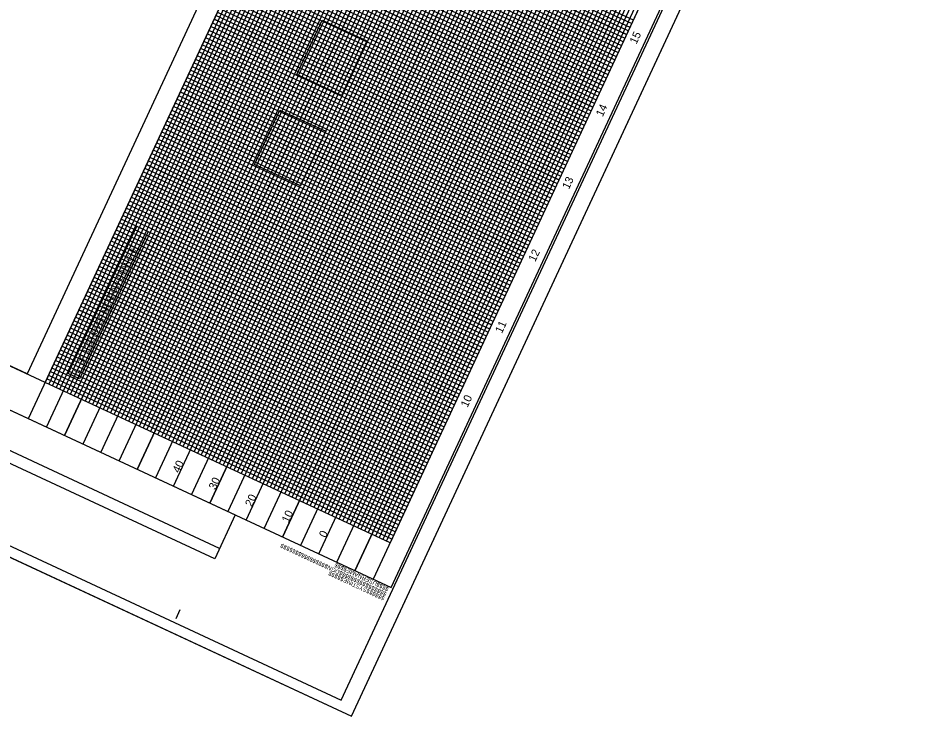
# Model space of a CAD drawing. Extents: x 2532214 to 2534758, y 714172 to 717266.
# Drawn here: x 2532790 to 2533904, y 714631 to 715503 of the extents above; entities that cross this region are included whole.
import ezdxf

# ---------------------------------------------------------------- set-up
doc = ezdxf.new("R2010")
doc.units = 0
for name, color, linetype in [('Arrowhead Terminators', 7, 'Continuous'), ('Auto Dimensioning', 7, 'Continuous'), ('Default', 7, 'Continuous'), ('Dimension Lines', 7, 'Continuous'), ('Dimension Lines CELL', 7, 'Continuous'), ('Mis Existing Structures', 7, 'Continuous'), ('Mis Ground Lines', 7, 'Continuous'), ('Peseal', 7, 'Continuous'), ('Plan Sheet', 7, 'Continuous'), ('Rebar Hooks Both Ends', 7, 'Continuous'), ('Rebar Lines', 7, 'Continuous'), ('Rebar with Hook on Left End', 7, 'Continuous'), ('Structural Steel Angle 3 x 3', 7, 'Continuous'), ('Structural Steel Channel 12', 7, 'Continuous'), ('Structural Steel Channel 12 Hidden', 7, 'Continuous'), ('Structural Steel Lines', 7, 'Continuous'), ('Sup Concrete Girder Lines', 7, 'Continuous')]:
    doc.layers.add(name, color=color, linetype=linetype)

msp = doc.modelspace()

# ---------------------------------------------------------------- linework, layer by layer
at = {"layer": 'Arrowhead Terminators'}
for p, q in [((2533206.9, 714631.3), (2533917.1, 716157.7)), ((2532214.1, 715093.2), (2533206.9, 714631.3))]:
    msp.add_line(p, q, dxfattribs=at)
at = {"layer": 'Auto Dimensioning'}
msp.add_line((2533042.4, 714840.8), (2532325.6, 715174.3), dxfattribs=at)
msp.add_lwpolyline([(2533036.3, 714827.6), (2532319.4, 715161.1), (2532345, 715216), (2533061.8, 714882.5)], close=True, dxfattribs=at)
at = {"layer": 'Default'}
for points in [[(2533138.6, 715432.4), (2533170.3, 715500.4), (2533226.2, 715474.4), (2533194.6, 715406.4)], [(2533138.6, 715432.4), (2533170.3, 715500.4), (2533226.2, 715474.4), (2533194.6, 715406.4)], [(2533086, 715320.1), (2533117.6, 715388.1), (2533174.9, 715361.5), (2533143.2, 715293.5)], [(2533086, 715320.1), (2533117.6, 715388.1), (2533174.9, 715361.5), (2533143.2, 715293.5)], [(2532853.4, 715059), (2532939, 715242.9), (2532953.1, 715236.4), (2532867.5, 715052.5)], [(2532853.4, 715059), (2532939, 715242.9), (2532953.1, 715236.4), (2532867.5, 715052.5)]]:
    msp.add_lwpolyline(points, close=True, dxfattribs=at)
at = {"layer": 'Dimension Lines'}
for p, q in [((2532826.1, 714992.1), (2533458.9, 716352.2)), ((2533504.2, 716331.1), (2532871.4, 714971.1)), ((2532916.8, 714950), (2533549.5, 716310)), ((2533594.9, 716288.9), (2532962.1, 714928.9)), ((2533007.4, 714907.8), (2533640.2, 716267.8)), ((2533685.5, 716246.7), (2533052.8, 714886.7)), ((2533098.1, 714865.6), (2533730.9, 716225.6)), ((2533776.2, 716204.5), (2533143.4, 714844.5)), ((2533188.8, 714823.4), (2533821.5, 716183.4)), ((2533109.3, 715660), (2533539.9, 715459.7)), ((2533518.8, 715414.3), (2533088.2, 715614.7)), ((2533067.1, 715569.4), (2533497.8, 715369)), ((2533476.7, 715323.7), (2533046, 715524)), ((2533024.9, 715478.7), (2533455.6, 715278.3)), ((2533434.5, 715233), (2533003.8, 715433.4)), ((2532982.7, 715388), (2533413.4, 715187.7)), ((2533392.3, 715142.3), (2532961.6, 715342.7)), ((2532940.5, 715297.4), (2533371.2, 715097)), ((2533350.1, 715051.7), (2532919.4, 715252)), ((2532898.4, 715206.7), (2533329, 715006.3)), ((2533307.9, 714961), (2532877.3, 715161.4)), ((2532856.2, 715116), (2533286.8, 714915.7)), ((2533265.8, 714870.3), (2532835.1, 715070.7))]:
    msp.add_line(p, q, dxfattribs=at)
at = {"layer": 'Dimension Lines CELL'}
msp.add_lwpolyline([(2533392.4, 716327.9), (2533206.8, 715929), (2532801.9, 715058.6), (2532325.9, 715280), (2532853.1, 716413.3), (2533042.4, 716325.3), (2533105.7, 716461.3), (2533324.4, 716359.6)], close=True, dxfattribs=at)
at = {"layer": 'Mis Existing Structures'}
msp.add_lwpolyline([(2533194.3, 714651.5), (2533897.1, 716162.1), (2532940.5, 716607.1), (2532237.8, 715096.6)], close=True, dxfattribs=at)
at = {"layer": 'Mis Ground Lines'}
msp.add_lwpolyline([(2533206.9, 714631.3), (2533917.1, 716157.7), (2532924.3, 716619.6), (2532214.1, 715093.2)], close=True, dxfattribs=at)
at = {"layer": 'Peseal'}
msp.add_line((2533256.8, 714791.8), (2533256.8, 714791.8), dxfattribs=at)
at = {"layer": 'Plan Sheet'}
for p, q in [((2532848.8, 714981.6), (2533460.4, 716296.3)), ((2532939.4, 714939.4), (2533572.2, 716299.4)), ((2532894.1, 714960.5), (2533505.8, 716275.2)), ((2532984.8, 714918.3), (2533617.5, 716278.3)), ((2533030.1, 714897.2), (2533662.9, 716257.2)), ((2533075.4, 714876.1), (2533708.2, 716236.2)), ((2533120.8, 714855), (2533753.5, 716215.1)), ((2533166.1, 714834), (2533798.9, 716194)), ((2533211.4, 714812.9), (2533844.2, 716172.9)), ((2533119.8, 715682.7), (2533550.5, 715482.3)), ((2533098.7, 715637.4), (2533529.4, 715437)), ((2533077.6, 715592), (2533508.3, 715391.7)), ((2533056.5, 715546.7), (2533487.2, 715346.3)), ((2533035.4, 715501.4), (2533466.1, 715301)), ((2533014.4, 715456), (2533445, 715255.7)), ((2532993.3, 715410.7), (2533423.9, 715210.3)), ((2532972.2, 715365.4), (2533402.8, 715165)), ((2532951.1, 715320), (2533381.8, 715119.7)), ((2532930, 715274.7), (2533360.7, 715074.3)), ((2532908.9, 715229.4), (2533339.6, 715029)), ((2532887.8, 715184), (2533318.5, 714983.7)), ((2532866.7, 715138.7), (2533297.4, 714938.3)), ((2532845.6, 715093.4), (2533276.3, 714893))]:
    msp.add_line(p, q, dxfattribs=at)
at = {"layer": 'Rebar Lines'}
for p, q in [((2533419.6, 716315.3), (2532829.1, 715045.9)), ((2532833.6, 715043.8), (2533424.2, 716313.2)), ((2533428.7, 716311), (2532838.1, 715041.7)), ((2532842.7, 715039.6), (2533433.2, 716308.9)), ((2533442.3, 716304.7), (2532851.7, 715035.4)), ((2532856.3, 715033.3), (2533446.8, 716302.6)), ((2533451.4, 716300.5), (2532860.8, 715031.1)), ((2532865.3, 715029), (2533455.9, 716298.4)), ((2533465, 716294.2), (2532874.4, 715024.8)), ((2532878.9, 715022.7), (2533469.5, 716292.1)), ((2533474, 716289.9), (2532883.5, 715020.6)), ((2532888, 715018.5), (2533478.6, 716287.8)), ((2533487.6, 716283.6), (2532897.1, 715014.3)), ((2532901.6, 715012.2), (2533492.2, 716281.5)), ((2533496.7, 716279.4), (2532906.1, 715010.1)), ((2532910.7, 715007.9), (2533501.2, 716277.3)), ((2532919.7, 715003.7), (2533510.3, 716273.1)), ((2533514.8, 716271), (2532924.3, 715001.6)), ((2532928.8, 714999.5), (2533519.4, 716268.9)), ((2533523.9, 716266.7), (2532933.3, 714997.4)), ((2532942.4, 714993.2), (2533533, 716262.5)), ((2533537.5, 716260.4), (2532946.9, 714991.1)), ((2532951.5, 714989), (2533542, 716258.3)), ((2533546.6, 716256.2), (2532956, 714986.9)), ((2532965.1, 714982.6), (2533555.6, 716252)), ((2533560.2, 716249.9), (2532969.6, 714980.5)), ((2532974.1, 714978.4), (2533564.7, 716247.8)), ((2533569.2, 716245.7), (2532978.7, 714976.3)), ((2532987.7, 714972.1), (2533578.3, 716241.4)), ((2533582.8, 716239.3), (2532992.3, 714970)), ((2532996.8, 714967.9), (2533587.4, 716237.2)), ((2533591.9, 716235.1), (2533001.3, 714965.8)), ((2533010.4, 714961.5), (2533601, 716230.9)), ((2533605.5, 716228.8), (2533014.9, 714959.4)), ((2533019.5, 714957.3), (2533610, 716226.7)), ((2533614.6, 716224.6), (2533024, 714955.2)), ((2533033.1, 714951), (2533623.6, 716220.3)), ((2533628.2, 716218.2), (2533037.6, 714948.9)), ((2533042.1, 714946.8), (2533632.7, 716216.1)), ((2533637.2, 716214), (2533046.7, 714944.7)), ((2533055.7, 714940.5), (2533646.3, 716209.8)), ((2533650.8, 716207.7), (2533060.3, 714938.3)), ((2533064.8, 714936.2), (2533655.4, 716205.6)), ((2533659.9, 716203.5), (2533069.3, 714934.1)), ((2533078.4, 714929.9), (2533669, 716199.3)), ((2533673.5, 716197.1), (2533082.9, 714927.8)), ((2533087.5, 714925.7), (2533678, 716195)), ((2533682.6, 716192.9), (2533092, 714923.6)), ((2533101.1, 714919.4), (2533691.6, 716188.7)), ((2533696.2, 716186.6), (2533105.6, 714917.3)), ((2533110.1, 714915.1), (2533700.7, 716184.5)), ((2533705.2, 716182.4), (2533114.7, 714913)), ((2533123.7, 714908.8), (2533714.3, 716178.2)), ((2533718.8, 716176.1), (2533128.3, 714906.7)), ((2533132.8, 714904.6), (2533723.4, 716173.9)), ((2533727.9, 716171.8), (2533137.3, 714902.5)), ((2533146.4, 714898.3), (2533737, 716167.6)), ((2533741.5, 716165.5), (2533150.9, 714896.2)), ((2533155.5, 714894.1), (2533746, 716163.4)), ((2533750.6, 716161.3), (2533160, 714891.9)), ((2533169.1, 714887.7), (2533759.6, 716157.1)), ((2533764.2, 716155), (2533173.6, 714885.6)), ((2533178.1, 714883.5), (2533768.7, 716152.9)), ((2533773.2, 716150.7), (2533182.7, 714881.4)), ((2533191.7, 714877.2), (2533782.3, 716146.5)), ((2533196.3, 714875.1), (2533786.8, 716144.4)), ((2533791.4, 716142.3), (2533200.8, 714873)), ((2533205.3, 714870.9), (2533795.9, 716140.2)), ((2533805, 716136), (2533214.4, 714866.6)), ((2533218.9, 714864.5), (2533809.5, 716133.9)), ((2533814, 716131.8), (2533223.5, 714862.4)), ((2533228, 714860.3), (2533818.6, 716129.7)), ((2533827.6, 716125.4), (2533237.1, 714856.1)), ((2533241.6, 714854), (2533832.2, 716123.3)), ((2533836.7, 716121.2), (2533246.1, 714851.9)), ((2533250.7, 714849.8), (2533841.2, 716119.1)), ((2533124, 715691.8), (2533554.7, 715491.4)), ((2533556.8, 715495.9), (2533126.1, 715696.3)), ((2533128.2, 715700.8), (2533558.9, 715500.5)), ((2533552.6, 715486.9), (2533121.9, 715687.2)), ((2533113.5, 715669.1), (2533544.2, 715468.7)), ((2533546.3, 715473.3), (2533115.6, 715673.6)), ((2533117.7, 715678.2), (2533548.4, 715477.8)), ((2533542, 715464.2), (2533111.4, 715664.6)), ((2533535.7, 715450.6), (2533105, 715651)), ((2533107.2, 715655.5), (2533537.8, 715455.1)), ((2533531.5, 715441.5), (2533100.8, 715641.9)), ((2533102.9, 715646.4), (2533533.6, 715446.1)), ((2533525.2, 715427.9), (2533094.5, 715628.3)), ((2533096.6, 715632.8), (2533527.3, 715432.5)), ((2533521, 715418.9), (2533090.3, 715619.2)), ((2533092.4, 715623.8), (2533523.1, 715423.4)), ((2533514.6, 715405.3), (2533084, 715605.6)), ((2533086.1, 715610.2), (2533516.7, 715409.8)), ((2533510.4, 715396.2), (2533079.7, 715596.6)), ((2533081.8, 715601.1), (2533512.5, 715400.7)), ((2533504.1, 715382.6), (2533073.4, 715583)), ((2533075.5, 715587.5), (2533506.2, 715387.1)), ((2533499.9, 715373.5), (2533069.2, 715573.9)), ((2533071.3, 715578.4), (2533502, 715378.1)), ((2533493.5, 715359.9), (2533062.9, 715560.3)), ((2533065, 715564.8), (2533495.6, 715364.5)), ((2533489.3, 715350.9), (2533058.6, 715551.2)), ((2533060.8, 715555.8), (2533491.4, 715355.4)), ((2533483, 715337.3), (2533052.3, 715537.6)), ((2533054.4, 715542.2), (2533485.1, 715341.8)), ((2533478.8, 715328.2), (2533048.1, 715528.6)), ((2533050.2, 715533.1), (2533480.9, 715332.7)), ((2533472.4, 715314.6), (2533041.8, 715515)), ((2533043.9, 715519.5), (2533474.6, 715319.1)), ((2533468.2, 715305.5), (2533037.6, 715505.9)), ((2533039.7, 715510.4), (2533470.3, 715310.1)), ((2533461.9, 715291.9), (2533031.2, 715492.3)), ((2533033.3, 715496.8), (2533464, 715296.5)), ((2533457.7, 715282.9), (2533027, 715483.2)), ((2533029.1, 715487.8), (2533459.8, 715287.4)), ((2533451.4, 715269.3), (2533020.7, 715469.6)), ((2533022.8, 715474.2), (2533453.5, 715273.8)), ((2533447.1, 715260.2), (2533016.5, 715460.6)), ((2533018.6, 715465.1), (2533449.2, 715264.7)), ((2533440.8, 715246.6), (2533010.1, 715447)), ((2533012.2, 715451.5), (2533442.9, 715251.1)), ((2533436.6, 715237.5), (2533005.9, 715437.9)), ((2533008, 715442.4), (2533438.7, 715242.1)), ((2533430.3, 715223.9), (2532999.6, 715424.3)), ((2533001.7, 715428.8), (2533432.4, 715228.5)), ((2533426, 715214.9), (2532995.4, 715415.2)), ((2532997.5, 715419.8), (2533428.2, 715219.4)), ((2532991.2, 715406.2), (2533421.8, 715205.8)), ((2533415.5, 715192.2), (2532984.8, 715392.6)), ((2532986.9, 715397.1), (2533417.6, 715196.7)), ((2533419.7, 715201.3), (2532989, 715401.6)), ((2532980.6, 715383.5), (2533411.3, 715183.1)), ((2533405, 715169.5), (2532974.3, 715369.9)), ((2532976.4, 715374.4), (2533407.1, 715174.1)), ((2533409.2, 715178.6), (2532978.5, 715379)), ((2532970.1, 715360.8), (2533400.7, 715160.5)), ((2533394.4, 715146.9), (2532963.7, 715347.2)), ((2532965.8, 715351.8), (2533396.5, 715151.4)), ((2533398.6, 715155.9), (2532968, 715356.3)), ((2532959.5, 715338.2), (2533390.2, 715137.8)), ((2533383.9, 715124.2), (2532953.2, 715324.6)), ((2532955.3, 715329.1), (2533386, 715128.7)), ((2533388.1, 715133.3), (2532957.4, 715333.6)), ((2532949, 715315.5), (2533379.6, 715115.1)), ((2533373.3, 715101.5), (2532942.6, 715301.9)), ((2532944.8, 715306.4), (2533375.4, 715106.1)), ((2533377.5, 715110.6), (2532946.9, 715311)), ((2532938.4, 715292.8), (2533369.1, 715092.5)), ((2532934.2, 715283.8), (2533364.9, 715083.4)), ((2533367, 715087.9), (2532936.3, 715288.3)), ((2532927.9, 715270.2), (2533358.6, 715069.8)), ((2533362.8, 715078.9), (2532932.1, 715279.2)), ((2532923.7, 715261.1), (2533354.3, 715060.7)), ((2533356.4, 715065.3), (2532925.8, 715265.6)), ((2532917.3, 715247.5), (2533348, 715047.1)), ((2533352.2, 715056.2), (2532921.6, 715256.6)), ((2532913.1, 715238.4), (2533343.8, 715038.1)), ((2533345.9, 715042.6), (2532915.2, 715243)), ((2532906.8, 715224.8), (2533337.5, 715024.5)), ((2533341.7, 715033.5), (2532911, 715233.9)), ((2532902.6, 715215.8), (2533333.2, 715015.4)), ((2533335.4, 715019.9), (2532904.7, 715220.3)), ((2532896.2, 715202.2), (2533326.9, 715001.8)), ((2533331.1, 715010.9), (2532900.5, 715211.2)), ((2532892, 715193.1), (2533322.7, 714992.7)), ((2533324.8, 714997.3), (2532894.1, 715197.6)), ((2532885.7, 715179.5), (2533316.4, 714979.1)), ((2533320.6, 714988.2), (2532889.9, 715188.6)), ((2532881.5, 715170.4), (2533312.2, 714970.1)), ((2533314.3, 714974.6), (2532883.6, 715175)), ((2533310, 714965.5), (2532879.4, 715165.9)), ((2532870.9, 715147.8), (2533301.6, 714947.4)), ((2533303.7, 714951.9), (2532873, 715152.3)), ((2532875.2, 715156.8), (2533305.8, 714956.5)), ((2533299.5, 714942.9), (2532868.8, 715143.2)), ((2532860.4, 715125.1), (2533291.1, 714924.7)), ((2533293.2, 714929.3), (2532862.5, 715129.6)), ((2532864.6, 715134.2), (2533295.3, 714933.8)), ((2533289, 714920.2), (2532858.3, 715120.6)), ((2532849.8, 715102.4), (2533280.5, 714902.1)), ((2533282.6, 714906.6), (2532852, 715107)), ((2532854.1, 715111.5), (2533284.7, 714911.1)), ((2533278.4, 714897.5), (2532847.7, 715097.9)), ((2532839.3, 715079.8), (2533270, 714879.4)), ((2533272.1, 714883.9), (2532841.4, 715084.3)), ((2532843.5, 715088.8), (2533274.2, 714888.5)), ((2533267.9, 714874.9), (2532837.2, 715075.2)), ((2532828.8, 715057.1), (2533259.4, 714856.7)), ((2533261.5, 714861.3), (2532830.9, 715061.6)), ((2532833, 715066.2), (2533263.6, 714865.8)), ((2533257.3, 714852.2), (2532826.6, 715052.6))]:
    msp.add_line(p, q, dxfattribs=at)
at = {"layer": 'Structural Steel Angle 3 x 3'}
msp.add_lwpolyline([(2532325.9, 715280), (2532853.1, 716413.3), (2533042.4, 716325.3), (2533126.8, 716506.7), (2533345.5, 716404.9), (2533138.8, 715960.6), (2533229.5, 715918.4), (2532824.5, 715048)], close=True, dxfattribs=at)
at = {"layer": 'Structural Steel Channel 12'}
msp.add_lwpolyline([(2532824.5, 715048), (2533229.5, 715918.4), (2533415.1, 716317.4), (2533539.1, 716259.7), (2533845.8, 716117), (2533255.2, 714847.7)], close=True, dxfattribs=at)
at = {"layer": 'Structural Steel Lines'}
for p, q in [((2533436.2, 716362.7), (2532803.4, 715002.7)), ((2533866.9, 716162.3), (2533234.1, 714802.3)), ((2533256.8, 714791.8), (2533256.8, 714791.8)), ((2533256.8, 714791.8), (2533256.8, 714791.8)), ((2533256.8, 714791.8), (2533256.8, 714791.8)), ((2533256.8, 714791.8), (2533256.8, 714791.8)), ((2533256.8, 714791.8), (2533256.8, 714791.8)), ((2532987.9, 714753.1), (2532993.1, 714764.4))]:
    msp.add_line(p, q, dxfattribs=at)
msp.add_lwpolyline([(2532937.5, 716594.7), (2532304.8, 715234.7), (2533256.8, 714791.8), (2533889.5, 716151.8)], close=True, dxfattribs=at)
at = {"layer": 'Sup Concrete Girder Lines'}
for p, q in [((2533481.5, 716341.6), (2532848.8, 714981.6)), ((2532894.1, 714960.5), (2533526.9, 716320.5)), ((2533572.2, 716299.4), (2532939.4, 714939.4)), ((2532984.8, 714918.3), (2533617.5, 716278.3)), ((2533662.9, 716257.2), (2533030.1, 714897.2)), ((2533075.4, 714876.1), (2533708.2, 716236.2)), ((2533753.5, 716215.1), (2533120.8, 714855)), ((2533166.1, 714834), (2533798.9, 716194)), ((2533844.2, 716172.9), (2533211.4, 714812.9)), ((2533550.5, 715482.3), (2533119.8, 715682.7)), ((2533098.7, 715637.4), (2533529.4, 715437)), ((2533508.3, 715391.7), (2533077.6, 715592)), ((2533056.5, 715546.7), (2533487.2, 715346.3)), ((2533466.1, 715301), (2533035.4, 715501.4)), ((2533014.4, 715456), (2533445, 715255.7)), ((2533423.9, 715210.3), (2532993.3, 715410.7)), ((2532972.2, 715365.4), (2533402.8, 715165)), ((2533381.8, 715119.7), (2532951.1, 715320)), ((2532930, 715274.7), (2533360.7, 715074.3)), ((2533339.6, 715029), (2532908.9, 715229.4)), ((2532887.8, 715184), (2533318.5, 714983.7)), ((2533297.4, 714938.3), (2532866.7, 715138.7)), ((2532845.6, 715093.4), (2533276.3, 714893)), ((2533255.2, 714847.7), (2532824.5, 715048))]:
    msp.add_line(p, q, dxfattribs=at)

# ---------------------------------------------------------------- texts
at = {"layer": 'Peseal'}
for s, p in [('$$$$$$$$$$$$$$$$DGN$$$$$$$$$$$$$$$$', (2533251.4, 714785.8)), ('$$$$USERNAME$$$$', (2533254.2, 714791.8)), ('$$$$$$SYSTIME$$$$$', (2533248.9, 714780.3))]:
    msp.add_text(s, height=5.25, rotation=155.05, dxfattribs=at).set_placement(p)
at = {"layer": 'Rebar Hooks Both Ends'}
for s, p in [('40', (2532991.9, 714934.2)), ('30', (2533037.2, 714913.1)), ('20', (2533082.6, 714892)), ('10', (2533128.4, 714872)), ('0', (2533174.9, 714853.4))]:
    msp.add_text(s, height=10, rotation=65.05, dxfattribs=at).set_placement(p)
at = {"layer": 'Rebar with Hook on Left End'}
for s, p in [('15', (2533562.9, 715469.6)), ('14', (2533520.7, 715378.9)), ('13', (2533478.6, 715288.4)), ('12', (2533436.5, 715197.8)), ('11', (2533394.9, 715108.5)), ('10', (2533351.9, 715016))]:
    msp.add_text(s, height=10, rotation=65.05, dxfattribs=at).set_placement(p)
at = {"layer": 'Structural Steel Channel 12 Hidden'}
msp.add_text('-L- SR 1552 (OVER MEADOW BRANCH)', height=7, rotation=65.05, dxfattribs=at).set_placement((2532865, 715056.1))

doc.saveas('drawing.dxf')
